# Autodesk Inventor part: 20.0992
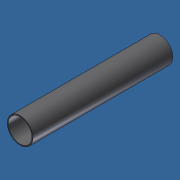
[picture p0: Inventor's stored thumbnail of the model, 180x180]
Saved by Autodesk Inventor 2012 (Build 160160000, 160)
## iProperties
Created: 2007-07
Part Number: 20.0992
Material: PVC-Piping
Document SubType Name: Modeling
Designer: Andy Moles
Density: 1.4 g/cm^3
Description: TUBE 50 PVC   L = SPECIFY
Vendor: F
Author: Andy Moles
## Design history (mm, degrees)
sketch "Sketch1"
  geometry: C1 r 23 at (0, 0); C2 r 25 at (0, 0); 1 further point
  constraints: 2 centre point, 2 coincident
  dimensions: "d0" = 46 diameter of C1; "d1" = 50 diameter of C2
extrude "Extrusion1" new body sketch "Sketch1" stored distance "d2" = 272 (= PVC_TUBE); taper "d3" = 0 deg
body "Solid1"
other parameters: "PVC_TUBE" = 272 (computed from FRAME_ID) [user parameter; used in 1 equation term]
